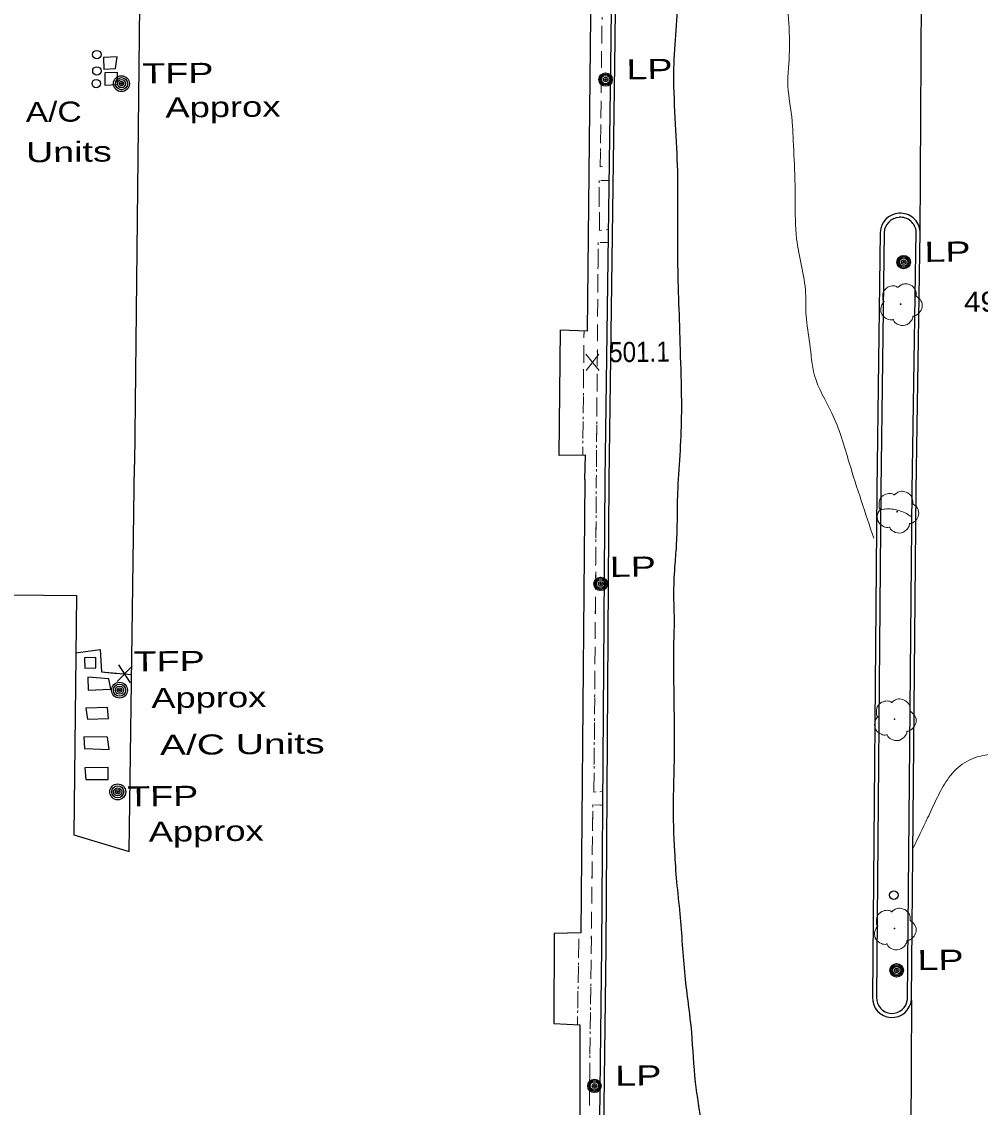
# Model space of a CAD drawing. Extents: x 2362213 to 2366494, y 6968794 to 6978110.
# Drawn here: x 2364004.9 to 2364233.7, y 6973596.3 to 6973855.4 of the extents above; entities that cross this region are included whole.
import ezdxf

# ---------------------------------------------------------------- set-up
doc = ezdxf.new("R2010")
doc.units = 0
doc.header["$LTSCALE"] = 1.9
doc.linetypes.add('DOTTED', pattern=[1.5, 0.3, -1.2])
doc.linetypes.add('LONG_DASH_SHORT_DASH', pattern=[9.9, 6, -1.2, 1.5, -1.2])
for name, color, linetype, lineweight in [('11', 7, 'Continuous', 25), ('13', 7, 'Continuous', 13), ('17', 7, 'Continuous', 25), ('2', 7, 'Continuous', 25), ('20', 7, 'Continuous', 25), ('23', 7, 'Continuous', 25), ('29', 7, 'Continuous', 13), ('31', 7, 'Continuous', 25), ('35', 7, 'Continuous', 13)]:
    doc.layers.add(name, color=color, linetype=linetype, lineweight=lineweight)

msp = doc.modelspace()

# ---------------------------------------------------------------- linework, layer by layer
at = {"layer": '11'}
for points in [[(2364139.343, 6973746.179), (2364139.477, 6973751.99), (2364133.208, 6973751.871), (2364133.472, 6973781.905), (2364139.915, 6973781.646), (2364141.21, 6973901.875), (2364134.979, 6973901.965), (2364135.343, 6973932.009), (2364141.404, 6973931.917), (2364142.032, 6973991.997), (2364135.834, 6973991.808), (2364136.363, 6974011.793), (2364034.69, 6974012.845), (2364031.804, 6973749.765)], [(2363882.575, 6973571.486), (2363883.372, 6973643.127), (2363860.452, 6973643.018), (2363860.826, 6973671.023), (2363883.517, 6973670.959), (2363884.282, 6973719.809), (2364017.991, 6973718.463), (2364017.316, 6973661.333), (2364030.594, 6973657.349), (2364031.804, 6973749.765)], [(2364139.343, 6973746.179), (2364138.354, 6973637.914), (2364132.025, 6973637.804), (2364131.95, 6973616.273), (2364138.143, 6973615.961), (2364138.145, 6973588.37)]]:
    msp.add_lwpolyline(points, dxfattribs=at)
at = {"layer": '13'}
for p, q in [((2364143.403, 6973854.433), (2364143.351, 6973850.433)), ((2364143.33, 6973848.431), (2364143.278, 6973844.431)), ((2364143.257, 6973842.43), (2364143.205, 6973838.43)), ((2364143.184, 6973836.43), (2364143.133, 6973832.43)), ((2364143.112, 6973830.43), (2364143.06, 6973826.428)), ((2364142.749, 6973815.944), (2364142.767, 6973811.945)), ((2364145.144, 6973817.547), (2364143.144, 6973817.548)), ((2364142.776, 6973809.945), (2364142.794, 6973805.945)), ((2364144.417, 6973805.751), (2364144.976, 6973805.816)), ((2364144.935, 6973802.765), (2364142.934, 6973802.756)), ((2364142.489, 6973801.181), (2364142.457, 6973797.181)), ((2364142.446, 6973795.181), (2364142.414, 6973791.18)), ((2364142.393, 6973789.181), (2364142.361, 6973785.18)), ((2364139.101, 6973779.978), (2364139.115, 6973781.678)), ((2364142.35, 6973783.18), (2364142.319, 6973779.179)), ((2364139.048, 6973773.977), (2364139.08, 6973777.978)), ((2364142.298, 6973777.178), (2364142.266, 6973773.178)), ((2364138.985, 6973767.976), (2364139.027, 6973771.977)), ((2364142.255, 6973771.178), (2364142.223, 6973767.178)), ((2364138.922, 6973761.977), (2364138.964, 6973765.977)), ((2364142.202, 6973765.178), (2364142.17, 6973761.177)), ((2364138.859, 6973755.975), (2364138.901, 6973759.975)), ((2364142.159, 6973759.176), (2364142.127, 6973755.176)), ((2364138.817, 6973751.974), (2364138.838, 6973753.974)), ((2364142.106, 6973753.175), (2364142.074, 6973749.175)), ((2364142.053, 6973746.125), (2364142.042, 6973744.125)), ((2364142.063, 6973747.175), (2364142.053, 6973746.125)), ((2364142.031, 6973742.125), (2364142, 6973738.125)), ((2364141.989, 6973736.124), (2364141.957, 6973732.123)), ((2364141.946, 6973730.123), (2364141.914, 6973726.122)), ((2364141.903, 6973724.122), (2364141.871, 6973720.123)), ((2364141.86, 6973718.123), (2364141.828, 6973714.121)), ((2364141.807, 6973712.121), (2364141.775, 6973708.12)), ((2364141.764, 6973706.12), (2364141.732, 6973702.12)), ((2364141.711, 6973700.119), (2364141.679, 6973696.12)), ((2364141.669, 6973694.12), (2364141.637, 6973690.118)), ((2364141.616, 6973688.118), (2364141.584, 6973684.117)), ((2364141.573, 6973682.117), (2364141.541, 6973678.117)), ((2364141.52, 6973676.116), (2364141.488, 6973672.117)), ((2364142.913, 6973671.639), (2364143.653, 6973671.687)), ((2364143.634, 6973668.416), (2364141.632, 6973668.527)), ((2364141.207, 6973666.963), (2364141.165, 6973662.962)), ((2364141.144, 6973660.962), (2364141.102, 6973656.962)), ((2364141.081, 6973654.961), (2364141.029, 6973650.962)), ((2364141.009, 6973648.96), (2364140.957, 6973644.96)), ((2364140.936, 6973642.959), (2364140.894, 6973638.959)), ((2364140.873, 6973636.958), (2364140.821, 6973632.958)), ((2364137.8, 6973631.999), (2364137.862, 6973636)), ((2364137.707, 6973625.998), (2364137.769, 6973629.999)), ((2364140.8, 6973630.957), (2364140.748, 6973626.957)), ((2364137.614, 6973619.997), (2364137.676, 6973623.997)), ((2364140.727, 6973624.957), (2364140.675, 6973620.956)), ((2364140.654, 6973618.956), (2364140.612, 6973614.955)), ((2364137.552, 6973615.996), (2364137.583, 6973617.996)), ((2364140.591, 6973612.955), (2364140.539, 6973608.954)), ((2364140.518, 6973606.954), (2364140.467, 6973602.953)), ((2364140.446, 6973600.953), (2364140.394, 6973596.952))]:
    msp.add_line(p, q, dxfattribs=at)
at = {"layer": '13', "linetype": 'DOTTED'}
for p, q in [((2364138.817, 6973751.974), (2364139.115, 6973781.678)), ((2364137.552, 6973615.996), (2364137.894, 6973637.91))]:
    msp.add_line(p, q, dxfattribs=at)
for points in [[(2364145.719, 6973862.255), (2364143.499, 6973862.214), (2364142.992, 6973820.827), (2364145.192, 6973820.958)], [(2364145.144, 6973817.547), (2364142.743, 6973817.544), (2364142.797, 6973805.575), (2364144.976, 6973805.816)], [(2364144.935, 6973802.765), (2364142.504, 6973802.751), (2364142.053, 6973746.125)], [(2364142.053, 6973746.125), (2364141.483, 6973671.546), (2364143.653, 6973671.687)], [(2364143.634, 6973668.416), (2364141.222, 6973668.553), (2364139.805, 6973546.394), (2364142.324, 6973546.488)]]:
    msp.add_lwpolyline(points, dxfattribs=at)
at = {"layer": '13'}
msp.add_lwpolyline([(2364143.039, 6973824.428), (2364142.992, 6973820.827), (2364143.393, 6973820.851)], dxfattribs=at)
at = {"layer": '17'}
for p, q in [((2364027.697, 6973697.913), (2364031.252, 6973701.608)), ((2364030.88, 6973697.624), (2364028.059, 6973701.897))]:
    msp.add_line(p, q, dxfattribs=at)
at = {"layer": '17', "linetype": 'LONG_DASH_SHORT_DASH'}
msp.add_lwpolyline([(2364017.831, 6973704.81), (2364023.674, 6973705.596), (2364023.955, 6973700.238), (2364031.142, 6973699.576)], dxfattribs=at)
at = {"layer": '17'}
msp.add_lwpolyline([(2364017.831, 6973704.81), (2364023.674, 6973705.596), (2364023.955, 6973700.238), (2364027.678, 6973699.893)], dxfattribs=at)
at = {"layer": '2'}
for p, q in [((2364219.352, 6973804.534), (2364219.676, 6973863.979)), ((2364209.805, 6973805.153), (2364208.989, 6973743.713)), ((2364210.765, 6973805.143), (2364209.95, 6973743.702)), ((2364217.463, 6973743.524), (2364218.404, 6973805.315)), ((2364218.423, 6973743.513), (2364219.364, 6973805.304)), ((2364208.989, 6973743.713), (2364207.963, 6973622.597)), ((2364209.95, 6973743.702), (2364208.923, 6973622.586)), ((2364216.299, 6973622.036), (2364217.463, 6973743.524)), ((2364217.259, 6973622.025), (2364218.423, 6973743.513)), ((2364217.241, 6973621.825), (2364217.046, 6973574.091))]:
    msp.add_line(p, q, dxfattribs=at)
for points in [[(2364144.154, 6973746.125), (2364145.605, 6973851.044), (2364147.091, 6973997.515), (2364147.554, 6974032.931), (2364210.69, 6974032.512), (2364220.151, 6974038.833), (2364220.339, 6974038.954)], [(2364145.115, 6973746.114), (2364146.566, 6973851.033), (2364148.051, 6973997.504), (2364148.503, 6974031.96), (2364210.979, 6974031.555), (2364221.871, 6974038.829)], [(2364141.081, 6973385.149), (2364141.2, 6973460.854), (2364158.023, 6973460.684), (2364158.976, 6973545.327), (2364142.313, 6973545.568), (2364143.407, 6973634.482), (2364144.154, 6973746.125)], [(2364142.041, 6973385.148), (2364142.159, 6973459.883), (2364158.971, 6973459.713), (2364159.947, 6973546.276), (2364143.285, 6973546.517), (2364144.368, 6973634.472), (2364145.115, 6973746.114)]]:
    msp.add_lwpolyline(points, dxfattribs=at)
for centre, radius, start, end in [((2364214.588, 6973804.919), 4.789, 94.14376, 177.20044), ((2364214.588, 6973804.919), 3.829, 94.14376, 177.20044), ((2364214.633, 6973804.969), 4.742, 4.04824, 94.73405), ((2364214.633, 6973804.969), 3.783, 4.04824, 94.73405), ((2364212.618, 6973622.417), 4.658, 177.7897, 355.17429), ((2364212.618, 6973622.417), 3.698, 177.7897, 355.17429)]:
    msp.add_arc(centre, radius, start, end, dxfattribs=at)
at = {"layer": '20'}
for centre, radius in [((2364028.718, 6973840.64), 1.9), ((2364028.718, 6973840.64), 1.442), ((2364028.718, 6973840.64), 0.973), ((2364028.718, 6973840.64), 0.539), ((2364144.275, 6973841.631), 1.6), ((2364144.275, 6973841.631), 1.3), ((2364144.275, 6973841.631), 1), ((2364144.275, 6973841.631), 0.539), ((2364144.275, 6973841.631), 0.192), ((2364028.718, 6973840.64), 0.192), ((2364215.403, 6973798.056), 1.6), ((2364215.403, 6973798.056), 1.3), ((2364215.403, 6973798.056), 1), ((2364215.403, 6973798.056), 0.539), ((2364215.403, 6973798.056), 0.192), ((2364143.081, 6973721.234), 1.6), ((2364143.081, 6973721.234), 1.3), ((2364143.081, 6973721.234), 1), ((2364143.081, 6973721.234), 0.539), ((2364143.081, 6973721.234), 0.192), ((2364028.257, 6973695.879), 1.9), ((2364028.257, 6973695.879), 1.442), ((2364028.257, 6973695.879), 0.973), ((2364028.257, 6973695.879), 0.539), ((2364028.257, 6973695.879), 0.192), ((2364027.828, 6973671.594), 1.9), ((2364027.828, 6973671.594), 1.442), ((2364027.828, 6973671.594), 0.973), ((2364027.828, 6973671.594), 0.539), ((2364027.828, 6973671.594), 0.192), ((2364213.733, 6973629.002), 1.6), ((2364213.733, 6973629.002), 1.3), ((2364213.733, 6973629.002), 1), ((2364213.733, 6973629.002), 0.539), ((2364213.733, 6973629.002), 0.192), ((2364141.612, 6973601.404), 1.6), ((2364141.612, 6973601.404), 1.3), ((2364141.612, 6973601.404), 1), ((2364141.612, 6973601.404), 0.539), ((2364141.612, 6973601.404), 0.192)]:
    msp.add_circle(centre, radius, dxfattribs=at)
at = {"layer": '23'}
for points in [[(2364027.657, 6973847.06), (2364024.419, 6973846.859), (2364024.545, 6973844.07), (2364027.324, 6973844.267)], [(2364027.763, 6973843.271), (2364024.763, 6973843.242), (2364024.722, 6973840.252), (2364027.74, 6973840.41)], [(2364022.572, 6973703.705), (2364019.933, 6973703.62), (2364020.016, 6973701.111), (2364022.626, 6973701.205)], [(2364025.7, 6973698.615), (2364020.727, 6973698.957), (2364020.746, 6973695.898), (2364026.204, 6973696.14)], [(2364025.396, 6973691.751), (2364020.247, 6973691.552), (2364020.582, 6973688.975), (2364025.661, 6973689.074)], [(2364025.413, 6973684.661), (2364019.742, 6973684.727), (2364019.899, 6973681.979), (2364025.811, 6973681.735)], [(2364025.562, 6973677.422), (2364019.993, 6973677.319), (2364020.19, 6973674.531), (2364025.58, 6973674.532)]]:
    msp.add_lwpolyline(points, close=True, dxfattribs=at)
for centre in [(2364022.842, 6973847.595), (2364022.849, 6973843.694), (2364022.698, 6973840.663)]:
    msp.add_circle(centre, 1, dxfattribs=at)
at = {"layer": '29'}
for centre in [(2364214.688, 6973788.019), (2364213.84, 6973738.488), (2364213.222, 6973688.94), (2364213.218, 6973638.977)]:
    msp.add_circle(centre, 0.1, dxfattribs=at)
at = {"layer": '29', "lineweight": 25}
msp.add_circle((2364213.062, 6973646.946), 1, dxfattribs=at)
at = {"layer": '29'}
for points in [[(2364210.723, 6973788.591), (2364210.743, 6973788.602), (2364210.662, 6973788.671), (2364210.426, 6973789.299), (2364210.464, 6973790.579), (2364211.352, 6973791.877), (2364212.657, 6973792.359), (2364213.779, 6973792.17), (2364214.01, 6973792.042), (2364214.08, 6973792.043), (2364214.13, 6973792.083), (2364214.477, 6973792.376), (2364215.343, 6973792.825), (2364216.554, 6973792.756), (2364217.669, 6973792.167), (2364218.403, 6973790.745), (2364218.411, 6973789.885)], [(2364218.401, 6973789.905), (2364219.541, 6973788.845), (2364219.826, 6973787.258), (2364219.119, 6973785.931), (2364218.464, 6973785.385), (2364217.796, 6973785.169), (2364217.646, 6973785.157), (2364217.627, 6973785.047), (2364217.306, 6973784.144), (2364215.767, 6973782.979), (2364213.874, 6973783.261), (2364212.975, 6973784.203), (2364212.904, 6973784.332), (2364212.784, 6973784.311), (2364211.573, 6973784.429), (2364210.303, 6973785.427), (2364209.958, 6973787.064), (2364210.328, 6973788.088), (2364210.654, 6973788.531), (2364210.723, 6973788.581)], [(2364209.875, 6973739.061), (2364209.895, 6973739.071), (2364209.814, 6973739.141), (2364209.578, 6973739.768), (2364209.616, 6973741.049), (2364210.503, 6973742.347), (2364211.809, 6973742.83), (2364212.931, 6973742.64), (2364213.162, 6973742.513), (2364213.232, 6973742.513), (2364213.282, 6973742.554), (2364213.629, 6973742.847), (2364214.495, 6973743.295), (2364215.705, 6973743.227), (2364216.821, 6973742.637), (2364217.555, 6973741.214), (2364217.563, 6973740.354)], [(2364217.553, 6973740.374), (2364218.693, 6973739.315), (2364218.978, 6973737.727), (2364218.27, 6973736.4), (2364217.616, 6973735.854), (2364216.948, 6973735.637), (2364216.798, 6973735.626), (2364216.779, 6973735.516), (2364216.457, 6973734.613), (2364214.918, 6973733.448), (2364213.026, 6973733.73), (2364212.127, 6973734.671), (2364212.055, 6973734.801), (2364211.936, 6973734.78), (2364210.724, 6973734.898), (2364209.455, 6973735.896), (2364209.108, 6973737.533), (2364209.479, 6973738.557), (2364209.805, 6973739), (2364209.875, 6973739.051)], [(2364209.255, 6973689.512), (2364209.275, 6973689.522), (2364209.195, 6973689.591), (2364208.959, 6973690.219), (2364208.997, 6973691.5), (2364209.885, 6973692.798), (2364211.191, 6973693.281), (2364212.313, 6973693.091), (2364212.544, 6973692.963), (2364212.614, 6973692.964), (2364212.663, 6973693.005), (2364213.011, 6973693.298), (2364213.876, 6973693.746), (2364215.087, 6973693.678), (2364216.203, 6973693.088), (2364216.936, 6973691.665), (2364216.944, 6973690.805)], [(2364216.934, 6973690.825), (2364218.074, 6973689.766), (2364218.36, 6973688.179), (2364217.652, 6973686.852), (2364216.997, 6973686.306), (2364216.329, 6973686.089), (2364216.179, 6973686.078), (2364216.161, 6973685.968), (2364215.839, 6973685.064), (2364214.3, 6973683.9), (2364212.407, 6973684.182), (2364211.508, 6973685.123), (2364211.437, 6973685.253), (2364211.317, 6973685.231), (2364210.106, 6973685.35), (2364208.836, 6973686.348), (2364208.49, 6973687.985), (2364208.86, 6973689.008), (2364209.186, 6973689.451), (2364209.256, 6973689.502)], [(2364209.251, 6973639.55), (2364209.271, 6973639.56), (2364209.19, 6973639.629), (2364208.954, 6973640.257), (2364208.992, 6973641.537), (2364209.881, 6973642.836), (2364211.186, 6973643.318), (2364212.308, 6973643.129), (2364212.54, 6973643.001), (2364212.609, 6973643.002), (2364212.659, 6973643.042), (2364213.006, 6973643.336), (2364213.872, 6973643.784), (2364215.083, 6973643.715), (2364216.198, 6973643.126), (2364216.932, 6973641.703), (2364216.94, 6973640.843)], [(2364216.93, 6973640.863), (2364218.07, 6973639.804), (2364218.355, 6973638.216), (2364217.648, 6973636.89), (2364216.993, 6973636.343), (2364216.325, 6973636.127), (2364216.175, 6973636.115), (2364216.156, 6973636.005), (2364215.835, 6973635.102), (2364214.296, 6973633.937), (2364212.403, 6973634.219), (2364211.504, 6973635.161), (2364211.433, 6973635.29), (2364211.313, 6973635.269), (2364210.102, 6973635.388), (2364208.831, 6973636.386), (2364208.486, 6973638.022), (2364208.856, 6973639.046), (2364209.182, 6973639.489), (2364209.251, 6973639.54)]]:
    msp.add_spline(points, degree=3, dxfattribs=at)
at = {"layer": '31', "lineweight": 13}
for p, q in [((2364142.695, 6973772.192), (2364139.578, 6973776.042)), ((2364139.615, 6973772.163), (2364142.658, 6973776.072))]:
    msp.add_line(p, q, dxfattribs=at)
at = {"layer": '31'}
for points in [[(2364164.084, 6973933.133), (2364164.064, 6973927.793), (2364163.759, 6973922.08), (2364163.315, 6973916.186), (2364162.993, 6973909.011), (2364162.945, 6973902.572), (2364162.802, 6973895.47), (2364162.595, 6973889.897), (2364162.433, 6973883.806), (2364162.239, 6973873.704), (2364162.035, 6973867.82), (2364161.635, 6973861.586), (2364160.914, 6973852.25), (2364160.491, 6973843.085), (2364160.896, 6973830.979), (2364161.393, 6973819.752), (2364161.446, 6973813.143), (2364161.439, 6973799.152), (2364161.544, 6973793.442), (2364161.884, 6973782.906), (2364162.095, 6973775.497), (2364162.36, 6973763.36), (2364161.524, 6973745.1)], [(2364161.524, 6973745.1), (2364161.452, 6973743.24), (2364161.365, 6973740.769), (2364161.322, 6973736.938), (2364161.15, 6973730.846), (2364160.796, 6973726.012), (2364160.489, 6973719.4), (2364160.613, 6973711.54), (2364160.475, 6973706.178), (2364160.542, 6973694.909), (2364160.624, 6973687.359), (2364160.56, 6973676.188), (2364160.386, 6973669.296), (2364160.709, 6973657.368), (2364161.208, 6973650.134), (2364161.991, 6973642.52), (2364163.162, 6973627.711), (2364164.74, 6973614.215), (2364165.655, 6973602.293), (2364167.041, 6973592.206), (2364167.53, 6973586.05), (2364169.509, 6973570.378), (2364172.115, 6973559.221), (2364174.294, 6973549.883), (2364176.531, 6973542.904), (2364180.637, 6973532.802), (2364184.475, 6973524.579), (2364186.698, 6973522.14)]]:
    msp.add_spline(points, degree=3, dxfattribs=at)
at = {"layer": '35'}
for points in [[(2364148.371, 6974021.678), (2364148.954, 6974021.354), (2364151.991, 6974020.653), (2364153.677, 6974019.919), (2364157.123, 6974016.121), (2364160.453, 6974013.013), (2364162.966, 6974010.557), (2364166.613, 6974005.721), (2364167.481, 6974003.859), (2364170.212, 6973999.565), (2364173.017, 6973994.852), (2364175.775, 6973988.848), (2364177.843, 6973982.657), (2364179.739, 6973977.784), (2364184.333, 6973966.908), (2364186.468, 6973961.138), (2364187.979, 6973952.712), (2364188.563, 6973946.038), (2364188.756, 6973939.359), (2364188.972, 6973935.61), (2364188.804, 6973928.089), (2364188.552, 6973923.036), (2364187.536, 6973914.215), (2364187.345, 6973908.013), (2364186.717, 6973900.348), (2364186.564, 6973892.265), (2364185.885, 6973885.778), (2364185.573, 6973876.626), (2364186.845, 6973868.017), (2364187.859, 6973857.217), (2364188.161, 6973848.558), (2364187.802, 6973840.095), (2364188.792, 6973831.685), (2364189.006, 6973828.106), (2364189.422, 6973819.069), (2364189.543, 6973812.701), (2364189.849, 6973803.622), (2364192.013, 6973790.653), (2364192.114, 6973785.254), (2364193.007, 6973778.591), (2364194.13, 6973771.022), (2364198.266, 6973762.022), (2364202.429, 6973750.13), (2364208.269, 6973732.145)], [(2364260.134, 6973844.433), (2364258.916, 6973846.282), (2364258.173, 6973850.826), (2364256.71, 6973856.302), (2364255.594, 6973860.072), (2364253.847, 6973866.125), (2364252.382, 6973869.681), (2364249.48, 6973876.104), (2364246.741, 6973882.459), (2364243.879, 6973886.821), (2364241.49, 6973887.818), (2364238.103, 6973888.516), (2364235.253, 6973888.469), (2364231.498, 6973887.973), (2364226.798, 6973884.648), (2364223.94, 6973879.341), (2364221.96, 6973871.892), (2364219.7, 6973865.599)], [(2364217.403, 6973737.212), (2364215.904, 6973738.088), (2364212.975, 6973739.041), (2364211.404, 6973739.136), (2364209.906, 6973738.911)], [(2364257.88, 6973655.743), (2364255.966, 6973658.245), (2364253.95, 6973663.066), (2364250.436, 6973668.683), (2364247.875, 6973671.97), (2364244.72, 6973675.609), (2364241.215, 6973679.306), (2364239.223, 6973680.577), (2364237.452, 6973680.64), (2364233.318, 6973680.021), (2364228.908, 6973677.839), (2364225.485, 6973673.957), (2364223.185, 6973669.764), (2364221.127, 6973665.364), (2364217.606, 6973658.05)]]:
    msp.add_spline(points, degree=3, dxfattribs=at)

# ---------------------------------------------------------------- texts
at = {"layer": '20'}
for s, width, p in [('  LP', 1.4, (2364144.275, 6973841.63)), ('  TFP', 1.4, (2364028.718, 6973840.64)), ('Approx', 1.35, (2364039.237, 6973832.55)), ('  LP', 1.4, (2364215.403, 6973798.055)), ('  LP', 1.4, (2364140.305, 6973722.857)), ('  TFP', 1.4, (2364026.645, 6973700.264)), ('Approx', 1.35, (2364035.859, 6973691.591)), ('  TFP', 1.4, (2364025.101, 6973668.067)), ('Approx', 1.35, (2364035.233, 6973659.684)), ('  LP', 1.4, (2364213.733, 6973629.002)), ('  LP', 1.4, (2364141.611, 6973601.404))]:
    msp.add_text(s, height=4.8, rotation=0.546, dxfattribs=dict(at, width=width)).set_placement(p)
at = {"layer": '23'}
for s, width, p in [('A/C', 1.25, (2364005.874, 6973831.473)), ('Units', 1.4, (2364005.966, 6973821.872)), ('A/C Units', 1.45, (2364037.926, 6973680.39))]:
    msp.add_text(s, height=4.8, rotation=0.546, dxfattribs=dict(at, width=width)).set_placement(p)
at = {"layer": '31'}
for s, width, p in [('498.7', 1.1, (2364229.846, 6973786.163)), ('501.1', 0.9, (2364145.138, 6973774.155))]:
    msp.add_text(s, height=4.8, rotation=0.546, dxfattribs=dict(at, width=width)).set_placement(p)

doc.saveas('drawing.dxf')
